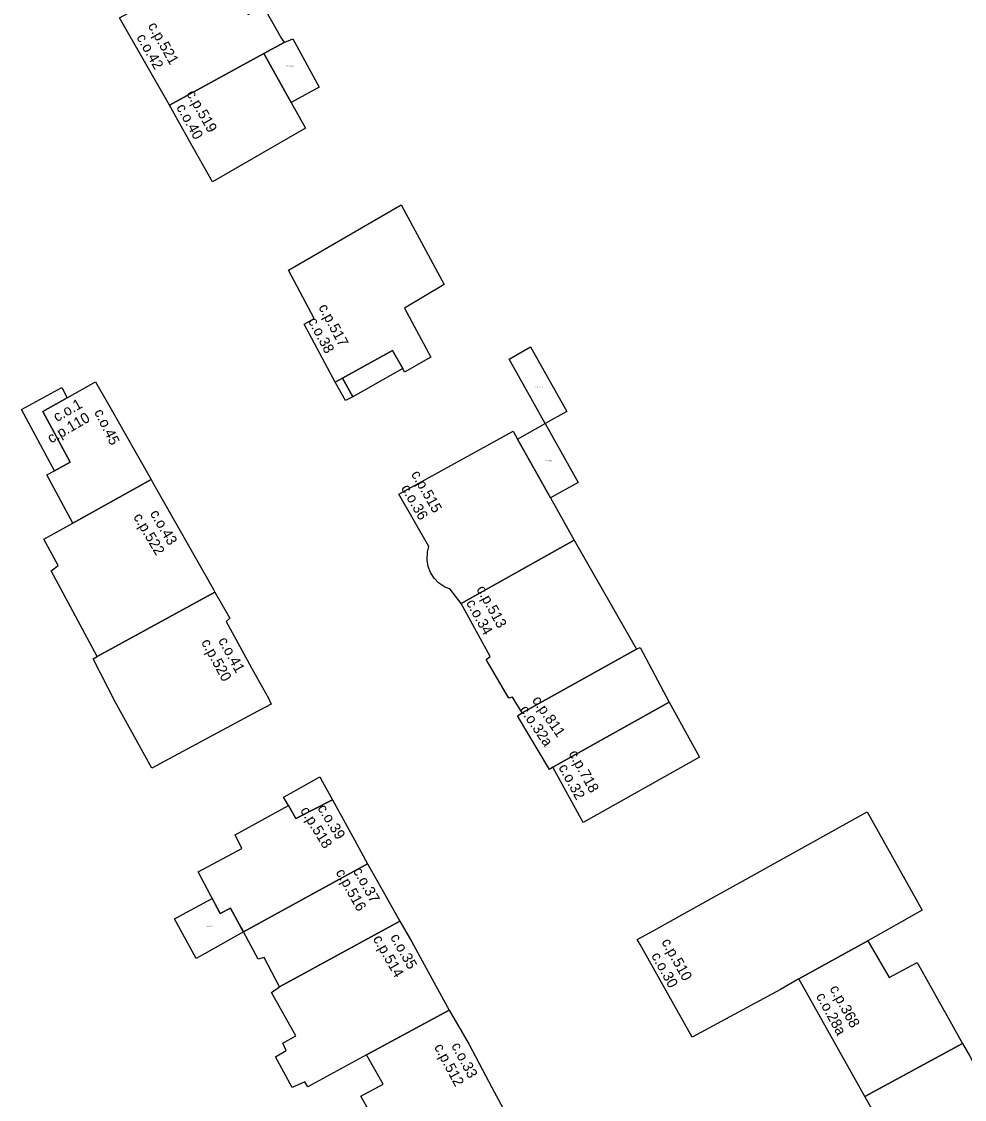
# Model space of a CAD drawing. Extents: x -600391 to -599491, y -1160176 to -1159402.
# Drawn here: x -600329.1 to -600239.1, y -1159820.9 to -1159718.1 of the extents above; entities that cross this region are included whole.
import ezdxf

# ---------------------------------------------------------------- set-up
doc = ezdxf.new("R2010")
doc.units = 0
for name, color, linetype in [('Level 10', 7, 'Continuous'), ('Level 12', 7, 'Continuous'), ('Level 25', 7, 'Continuous'), ('Level 61', 7, 'Continuous'), ('Level 62', 7, 'Continuous')]:
    doc.layers.add(name, color=color, linetype=linetype)

msp = doc.modelspace()

# ---------------------------------------------------------------- linework, layer by layer
at = {"layer": 'Level 61'}
for points in [[(-600306.02, -1159716.62), (-600304.28, -1159719.7)], [(-600314.98, -1159726.08), (-600319.73, -1159717.73)], [(-600304.28, -1159719.7), (-600304.03, -1159720.11)], [(-600304.03, -1159720.11), (-600303.21, -1159719.76)], [(-600303.21, -1159719.76), (-600300.69, -1159724.35)], [(-600304.03, -1159720.11), (-600305.98, -1159721.16)], [(-600305.98, -1159721.16), (-600304.03, -1159720.11)], [(-600305.98, -1159721.16), (-600314.98, -1159726.08)], [(-600314.98, -1159726.08), (-600305.98, -1159721.16)], [(-600305.98, -1159721.16), (-600303.36, -1159725.82)], [(-600303.36, -1159725.82), (-600305.98, -1159721.16)], [(-600300.69, -1159724.35), (-600303.36, -1159725.82)], [(-600313.98, -1159727.86), (-600314.98, -1159726.08)], [(-600303.36, -1159725.82), (-600301.99, -1159728.26)], [(-600313.82, -1159728.13), (-600313.98, -1159727.86)], [(-600313.29, -1159729.08), (-600313.82, -1159728.13)], [(-600313.05, -1159729.5), (-600313.29, -1159729.08)], [(-600301.99, -1159728.26), (-600310.86, -1159733.39)], [(-600310.86, -1159733.39), (-600313.05, -1159729.5)], [(-600303.61, -1159741.8), (-600292.85, -1159735.57)], [(-600292.85, -1159735.57), (-600288.77, -1159743.19)], [(-600301.17, -1159746.41), (-600303.61, -1159741.8)], [(-600288.77, -1159743.19), (-600292.56, -1159745.42)], [(-600292.56, -1159745.42), (-600290.03, -1159750.12)], [(-600302.11, -1159746.96), (-600301.17, -1159746.41)], [(-600299.17, -1159752.49), (-600302.11, -1159746.96)], [(-600298.45, -1159752.1), (-600293.69, -1159749.47)], [(-600293.69, -1159749.47), (-600298.45, -1159752.1)], [(-600293.69, -1159749.47), (-600292.72, -1159751.2)], [(-600292.72, -1159751.2), (-600293.69, -1159749.47)], [(-600282.56, -1159750.28), (-600280.51, -1159749.13)], [(-600280.51, -1159749.13), (-600277.07, -1159755.29)], [(-600290.03, -1159750.12), (-600292.55, -1159751.52)], [(-600279.11, -1159756.44), (-600282.56, -1159750.28)], [(-600292.72, -1159751.2), (-600297.48, -1159753.88)], [(-600292.55, -1159751.52), (-600292.72, -1159751.2)], [(-600324.72, -1159753.97), (-600322.02, -1159752.45)], [(-600322.02, -1159752.45), (-600320.4, -1159755.29)], [(-600298.45, -1159752.1), (-600299.17, -1159752.49)], [(-600299.17, -1159752.49), (-600298.45, -1159752.1)], [(-600298.16, -1159754.23), (-600299.17, -1159752.49)], [(-600297.48, -1159753.88), (-600298.45, -1159752.1)], [(-600298.45, -1159752.1), (-600297.48, -1159753.88)], [(-600329.08, -1159755.1), (-600325.25, -1159753)], [(-600325.25, -1159753), (-600324.72, -1159753.97)], [(-600297.48, -1159753.88), (-600298.16, -1159754.23)], [(-600327.04, -1159755.27), (-600324.72, -1159753.97)], [(-600324.72, -1159753.97), (-600327.04, -1159755.27)], [(-600325.94, -1159760.93), (-600329.08, -1159755.1)], [(-600324.43, -1159760.13), (-600327.04, -1159755.27)], [(-600327.04, -1159755.27), (-600324.43, -1159760.13)], [(-600320.4, -1159755.29), (-600319.32, -1159757.19)], [(-600277.07, -1159755.29), (-600279.11, -1159756.44)], [(-600281.75, -1159757.92), (-600279.11, -1159756.44)], [(-600279.11, -1159756.44), (-600275.97, -1159762.05)], [(-600319.32, -1159757.19), (-600316.72, -1159761.77)], [(-600293.08, -1159763.17), (-600282.17, -1159757.17)], [(-600282.17, -1159757.17), (-600281.75, -1159757.92)], [(-600281.75, -1159757.92), (-600278.62, -1159763.52)], [(-600278.62, -1159763.52), (-600281.75, -1159757.92)], [(-600326.67, -1159761.32), (-600325.94, -1159760.93)], [(-600325.94, -1159760.93), (-600324.43, -1159760.13)], [(-600324.43, -1159760.13), (-600325.94, -1159760.93)], [(-600324.18, -1159765.92), (-600326.67, -1159761.32)], [(-600324.18, -1159765.92), (-600316.72, -1159761.77)], [(-600316.72, -1159761.77), (-600324.18, -1159765.92)], [(-600316.72, -1159761.77), (-600316.58, -1159762.02)], [(-600316.58, -1159762.02), (-600316.45, -1159762.26)], [(-600275.97, -1159762.05), (-600278.62, -1159763.52)], [(-600316.45, -1159762.26), (-600312.78, -1159768.72)], [(-600290.22, -1159768.16), (-600293.08, -1159763.17)], [(-600278.62, -1159763.52), (-600276.37, -1159767.54)], [(-600326.96, -1159767.46), (-600324.18, -1159765.92)], [(-600325.6, -1159769.96), (-600326.96, -1159767.46)], [(-600290.35, -1159768.68), (-600290.22, -1159768.16)], [(-600287.15, -1159773.61), (-600276.37, -1159767.54)], [(-600276.37, -1159767.54), (-600287.15, -1159773.61)], [(-600276.37, -1159767.54), (-600270.4, -1159777.96)], [(-600312.78, -1159768.72), (-600310.81, -1159772.2)], [(-600290.39, -1159769.43), (-600290.35, -1159768.68)], [(-600326.26, -1159770.49), (-600325.6, -1159769.96)], [(-600290.3, -1159770.07), (-600290.39, -1159769.43)], [(-600290.07, -1159770.63), (-600290.3, -1159770.07)], [(-600321.85, -1159778.65), (-600326.26, -1159770.49)], [(-600289.72, -1159771.17), (-600290.07, -1159770.63)], [(-600289.31, -1159771.61), (-600289.72, -1159771.17)], [(-600310.81, -1159772.2), (-600310.64, -1159772.5)], [(-600288.73, -1159772), (-600289.31, -1159771.61)], [(-600288.19, -1159772.24), (-600288.73, -1159772)], [(-600287.15, -1159773.61), (-600288.19, -1159772.24)], [(-600310.64, -1159772.5), (-600321.85, -1159778.65)], [(-600321.85, -1159778.65), (-600310.64, -1159772.5)], [(-600310.64, -1159772.5), (-600309.2, -1159775)], [(-600284.37, -1159778.66), (-600287.15, -1159773.61)], [(-600309.2, -1159775), (-600309.56, -1159775.31)], [(-600309.56, -1159775.31), (-600306.96, -1159780.08)], [(-600270.4, -1159777.96), (-600281.32, -1159784.02)], [(-600281.32, -1159784.02), (-600270.4, -1159777.96)], [(-600270.4, -1159777.96), (-600270.06, -1159777.8)], [(-600270.06, -1159777.8), (-600267.31, -1159783.02)], [(-600322.24, -1159778.87), (-600321.85, -1159778.65)], [(-600320.14, -1159782.97), (-600322.24, -1159778.87)], [(-600284.75, -1159778.94), (-600284.37, -1159778.66)], [(-600282.59, -1159782.61), (-600284.75, -1159778.94)], [(-600306.96, -1159780.08), (-600305.51, -1159782.63)], [(-600305.51, -1159782.63), (-600305.27, -1159783.18)], [(-600282.23, -1159782.53), (-600282.59, -1159782.61)], [(-600281.32, -1159784.02), (-600282.23, -1159782.53)], [(-600316.64, -1159789.29), (-600320.14, -1159782.97)], [(-600305.27, -1159783.18), (-600307.03, -1159784.13)], [(-600267.31, -1159783.02), (-600278.4, -1159789.21)], [(-600278.4, -1159789.21), (-600267.31, -1159783.02)], [(-600267.31, -1159783.02), (-600264.4, -1159788.24)], [(-600307.03, -1159784.13), (-600316.64, -1159789.29)], [(-600281.75, -1159784.3), (-600281.32, -1159784.02)], [(-600278.72, -1159789.43), (-600281.75, -1159784.3)], [(-600264.4, -1159788.24), (-600275.51, -1159794.48)], [(-600278.4, -1159789.21), (-600278.72, -1159789.43)], [(-600275.51, -1159794.48), (-600278.4, -1159789.21)], [(-600303.38, -1159791.67), (-600300.61, -1159790.14)], [(-600300.61, -1159790.14), (-600300.37, -1159790.6)], [(-600300.37, -1159790.6), (-600299.43, -1159792.33)], [(-600304.08, -1159792.05), (-600303.38, -1159791.67)], [(-600308.7, -1159795.67), (-600303.62, -1159792.85)], [(-600303.62, -1159792.85), (-600304.08, -1159792.05)], [(-600303.62, -1159792.85), (-600302.91, -1159794.1)], [(-600302.91, -1159794.1), (-600303.62, -1159792.85)], [(-600302.91, -1159794.1), (-600299.43, -1159792.33)], [(-600299.43, -1159792.33), (-600302.91, -1159794.1)], [(-600299.43, -1159792.33), (-600297.51, -1159795.78)], [(-600261.16, -1159800.55), (-600248.4, -1159793.47)], [(-600248.4, -1159793.47), (-600243.17, -1159802.85)], [(-600308.05, -1159796.95), (-600308.7, -1159795.67)], [(-600297.51, -1159795.78), (-600296.06, -1159798.41)], [(-600312.23, -1159799.2), (-600308.05, -1159796.95)], [(-600296.06, -1159798.41), (-600307.89, -1159804.92)], [(-600307.89, -1159804.92), (-600296.06, -1159798.41)], [(-600296.06, -1159798.41), (-600295.02, -1159800.28)], [(-600310.12, -1159803.15), (-600312.23, -1159799.2)], [(-600295.02, -1159800.28), (-600293, -1159803.9)], [(-600262.73, -1159801.42), (-600261.16, -1159800.55)], [(-600314.5, -1159803.67), (-600310.88, -1159801.73)], [(-600310.88, -1159801.73), (-600310.12, -1159803.15)], [(-600267.45, -1159804.04), (-600262.73, -1159801.42)], [(-600310.12, -1159803.15), (-600309.13, -1159802.66)], [(-600309.13, -1159802.66), (-600310.12, -1159803.15)], [(-600309.13, -1159802.66), (-600308.13, -1159804.51)], [(-600308.13, -1159804.51), (-600309.13, -1159802.66)], [(-600243.17, -1159802.85), (-600248.34, -1159805.75)], [(-600312.41, -1159807.44), (-600314.5, -1159803.67)], [(-600293, -1159803.9), (-600304.47, -1159810.14)], [(-600304.47, -1159810.14), (-600293, -1159803.9)], [(-600293, -1159803.9), (-600291.85, -1159805.87)], [(-600268.77, -1159804.77), (-600267.45, -1159804.04)], [(-600307.89, -1159804.92), (-600310.83, -1159806.56)], [(-600308.13, -1159804.51), (-600307.89, -1159804.92)], [(-600307.89, -1159804.92), (-600308.13, -1159804.51)], [(-600306.5, -1159807.52), (-600307.89, -1159804.92)], [(-600270.34, -1159805.64), (-600268.77, -1159804.77)], [(-600291.85, -1159805.87), (-600290.66, -1159808.02)], [(-600270.06, -1159806.13), (-600270.34, -1159805.64)], [(-600265.1, -1159814.95), (-600270.06, -1159806.13)], [(-600248.34, -1159805.75), (-600254.91, -1159809.39)], [(-600254.91, -1159809.39), (-600248.34, -1159805.75)], [(-600248.34, -1159805.75), (-600246.3, -1159809.26)], [(-600310.83, -1159806.56), (-600312.41, -1159807.44)], [(-600305.93, -1159807.36), (-600306.5, -1159807.52)], [(-600304.47, -1159810.14), (-600305.93, -1159807.36)], [(-600290.66, -1159808.02), (-600288.29, -1159812.37)], [(-600246.3, -1159809.26), (-600243.65, -1159807.83)], [(-600243.65, -1159807.83), (-600239.3, -1159815.54)], [(-600254.91, -1159809.39), (-600256.68, -1159810.41)], [(-600248.62, -1159820.62), (-600254.91, -1159809.39)], [(-600305.23, -1159810.68), (-600304.47, -1159810.14)], [(-600256.68, -1159810.41), (-600265.1, -1159814.95)], [(-600302.92, -1159814.82), (-600305.23, -1159810.68)], [(-600296.16, -1159816.64), (-600288.29, -1159812.37)], [(-600288.29, -1159812.37), (-600296.16, -1159816.64)], [(-600288.29, -1159812.37), (-600286.39, -1159815.66)], [(-600304.16, -1159815.51), (-600302.92, -1159814.82)], [(-600303.84, -1159816.23), (-600304.16, -1159815.51)], [(-600239.3, -1159815.54), (-600248.62, -1159820.62)], [(-600248.62, -1159820.62), (-600239.3, -1159815.54)], [(-600239.3, -1159815.54), (-600238.62, -1159816.77)], [(-600304.86, -1159816.84), (-600303.84, -1159816.23)], [(-600286.39, -1159815.66), (-600284.2, -1159819.76)], [(-600303.27, -1159819.76), (-600304.86, -1159816.84)], [(-600296.16, -1159816.64), (-600301.78, -1159819.69)], [(-600294.57, -1159819.44), (-600296.16, -1159816.64)], [(-600302.05, -1159819.2), (-600303.27, -1159819.76)], [(-600301.78, -1159819.69), (-600302.05, -1159819.2)], [(-600296.72, -1159820.57), (-600294.57, -1159819.44)], [(-600290.35, -1159831.88), (-600296.72, -1159820.57)], [(-600284.2, -1159819.76), (-600280.6, -1159826.47)], [(-600240.34, -1159835.38), (-600248.62, -1159820.62)]]:
    msp.add_lwpolyline(points, dxfattribs=at)
at = {"layer": 'Level 62'}
for points in [[(-600305.98, -1159721.16), (-600314.98, -1159726.08), (-600319.73, -1159717.73), (-600316.55, -1159716), (-600312.59, -1159713.84), (-600310.26, -1159712.57), (-600307.47, -1159717.43), (-600306.02, -1159716.62), (-600304.28, -1159719.7), (-600304.03, -1159720.11), (-600305.98, -1159721.16)], [(-600300.69, -1159724.35), (-600303.36, -1159725.82), (-600305.98, -1159721.16), (-600304.03, -1159720.11), (-600303.21, -1159719.76), (-600300.69, -1159724.35)], [(-600314.98, -1159726.08), (-600305.98, -1159721.16), (-600303.36, -1159725.82), (-600301.99, -1159728.26), (-600310.86, -1159733.39), (-600313.05, -1159729.5), (-600313.29, -1159729.08), (-600313.82, -1159728.13), (-600313.98, -1159727.86), (-600314.98, -1159726.08)], [(-600299.17, -1159752.49), (-600302.11, -1159746.96), (-600301.17, -1159746.41), (-600303.61, -1159741.8), (-600292.85, -1159735.57), (-600288.77, -1159743.19), (-600292.56, -1159745.42), (-600290.03, -1159750.12), (-600292.55, -1159751.52), (-600292.72, -1159751.2), (-600293.69, -1159749.47), (-600298.45, -1159752.1), (-600299.17, -1159752.49)], [(-600297.48, -1159753.88), (-600298.45, -1159752.1), (-600293.69, -1159749.47), (-600292.72, -1159751.2), (-600297.48, -1159753.88)], [(-600280.51, -1159749.13), (-600277.07, -1159755.29), (-600279.11, -1159756.44), (-600282.56, -1159750.28), (-600280.51, -1159749.13)], [(-600319.32, -1159757.19), (-600316.72, -1159761.77), (-600324.18, -1159765.92), (-600326.67, -1159761.32), (-600325.94, -1159760.93), (-600324.43, -1159760.13), (-600327.04, -1159755.27), (-600324.72, -1159753.97), (-600322.02, -1159752.45), (-600320.4, -1159755.29), (-600319.32, -1159757.19)], [(-600299.17, -1159752.49), (-600298.45, -1159752.1), (-600297.48, -1159753.88), (-600298.16, -1159754.23), (-600299.17, -1159752.49)], [(-600325.25, -1159753), (-600324.72, -1159753.97), (-600327.04, -1159755.27), (-600324.43, -1159760.13), (-600325.94, -1159760.93), (-600329.08, -1159755.1), (-600325.25, -1159753)], [(-600281.75, -1159757.92), (-600279.11, -1159756.44), (-600275.97, -1159762.05), (-600278.62, -1159763.52), (-600281.75, -1159757.92)], [(-600281.75, -1159757.92), (-600278.62, -1159763.52), (-600276.37, -1159767.54), (-600287.15, -1159773.61), (-600288.19, -1159772.24), (-600288.73, -1159772), (-600289.31, -1159771.61), (-600289.72, -1159771.17), (-600290.07, -1159770.63), (-600290.3, -1159770.07), (-600290.39, -1159769.43), (-600290.35, -1159768.68), (-600290.22, -1159768.16), (-600293.08, -1159763.17), (-600282.17, -1159757.17), (-600281.75, -1159757.92)], [(-600310.81, -1159772.2), (-600310.64, -1159772.5), (-600321.85, -1159778.65), (-600326.26, -1159770.49), (-600325.6, -1159769.96), (-600326.96, -1159767.46), (-600324.18, -1159765.92), (-600316.72, -1159761.77), (-600316.58, -1159762.02), (-600316.45, -1159762.26), (-600312.78, -1159768.72), (-600310.81, -1159772.2)], [(-600270.4, -1159777.96), (-600281.32, -1159784.02), (-600282.23, -1159782.53), (-600282.59, -1159782.61), (-600284.75, -1159778.94), (-600284.37, -1159778.66), (-600287.15, -1159773.61), (-600276.37, -1159767.54), (-600270.4, -1159777.96)], [(-600305.51, -1159782.63), (-600305.27, -1159783.18), (-600307.03, -1159784.13), (-600316.64, -1159789.29), (-600320.14, -1159782.97), (-600322.24, -1159778.87), (-600321.85, -1159778.65), (-600310.64, -1159772.5), (-600309.2, -1159775), (-600309.56, -1159775.31), (-600306.96, -1159780.08), (-600305.51, -1159782.63)], [(-600278.72, -1159789.43), (-600281.75, -1159784.3), (-600281.32, -1159784.02), (-600270.4, -1159777.96), (-600270.06, -1159777.8), (-600267.31, -1159783.02), (-600278.4, -1159789.21), (-600278.72, -1159789.43)], [(-600278.4, -1159789.21), (-600267.31, -1159783.02), (-600264.4, -1159788.24), (-600275.51, -1159794.48), (-600278.4, -1159789.21)], [(-600303.38, -1159791.67), (-600300.61, -1159790.14), (-600300.37, -1159790.6), (-600299.43, -1159792.33), (-600302.91, -1159794.1), (-600303.62, -1159792.85), (-600304.08, -1159792.05), (-600303.38, -1159791.67)], [(-600303.62, -1159792.85), (-600302.91, -1159794.1), (-600299.43, -1159792.33), (-600297.51, -1159795.78), (-600296.06, -1159798.41), (-600307.89, -1159804.92), (-600308.13, -1159804.51), (-600309.13, -1159802.66), (-600310.12, -1159803.15), (-600312.23, -1159799.2), (-600308.05, -1159796.95), (-600308.7, -1159795.67), (-600303.62, -1159792.85)], [(-600267.45, -1159804.04), (-600262.73, -1159801.42), (-600261.16, -1159800.55), (-600248.4, -1159793.47), (-600243.17, -1159802.85), (-600248.34, -1159805.75), (-600254.91, -1159809.39), (-600256.68, -1159810.41), (-600265.1, -1159814.95), (-600270.06, -1159806.13), (-600270.34, -1159805.64), (-600268.77, -1159804.77), (-600267.45, -1159804.04)], [(-600296.06, -1159798.41), (-600295.02, -1159800.28), (-600293, -1159803.9), (-600304.47, -1159810.14), (-600305.93, -1159807.36), (-600306.5, -1159807.52), (-600307.89, -1159804.92), (-600296.06, -1159798.41)], [(-600312.41, -1159807.44), (-600314.5, -1159803.67), (-600310.88, -1159801.73), (-600310.12, -1159803.15), (-600309.13, -1159802.66), (-600308.13, -1159804.51), (-600307.89, -1159804.92), (-600310.83, -1159806.56), (-600312.41, -1159807.44)], [(-600305.23, -1159810.68), (-600304.47, -1159810.14), (-600293, -1159803.9), (-600291.85, -1159805.87), (-600290.66, -1159808.02), (-600288.29, -1159812.37), (-600296.16, -1159816.64), (-600301.78, -1159819.69), (-600302.05, -1159819.2), (-600303.27, -1159819.76), (-600304.86, -1159816.84), (-600303.84, -1159816.23), (-600304.16, -1159815.51), (-600302.92, -1159814.82), (-600305.23, -1159810.68)], [(-600254.91, -1159809.39), (-600248.34, -1159805.75), (-600246.3, -1159809.26), (-600243.65, -1159807.83), (-600239.3, -1159815.54), (-600248.62, -1159820.62), (-600254.91, -1159809.39)], [(-600288.29, -1159812.37), (-600286.39, -1159815.66), (-600284.2, -1159819.76), (-600280.6, -1159826.47), (-600290.35, -1159831.88), (-600296.72, -1159820.57), (-600294.57, -1159819.44), (-600296.16, -1159816.64), (-600288.29, -1159812.37)], [(-600231.22, -1159830.2), (-600240.34, -1159835.38), (-600248.62, -1159820.62), (-600239.3, -1159815.54), (-600238.62, -1159816.77), (-600237.94, -1159818), (-600232.57, -1159827.75), (-600231.9, -1159828.97), (-600231.22, -1159830.2)]]:
    msp.add_lwpolyline(points, dxfattribs=at)

# ---------------------------------------------------------------- texts
at = {"layer": 'Level 10'}
for s, rotation, p in [('c.o.42', 299.6362, (-600318.15, -1159719.6)), ('c.o.40', 299.4052, (-600314.35, -1159726.28)), ('c.o.38', 297.995, (-600301.78, -1159746.64)), ('c.o.1', 29.9929, (-600325.7, -1159756.31)), ('c.o.45', 296.3344, (-600322.18, -1159755.33)), ('c.o.36', 299.8209, (-600292.91, -1159762.58)), ('c.o.43', 300.6247, (-600316.87, -1159765.01)), ('c.o.34', 298.8359, (-600286.7, -1159773.52)), ('c.o.41', 298.7385, (-600310.35, -1159777.12)), ('c.o.32a', 304.3067, (-600281.61, -1159783.72)), ('c.o.32', 298.7385, (-600277.89, -1159789.22)), ('c.o.39', 301.7606, (-600300.89, -1159793.11)), ('c.o.37', 299.2282, (-600297.49, -1159799.08)), ('c.o.35', 299.5978, (-600293.94, -1159805.41)), ('c.o.30', 299.1976, (-600269.04, -1159807.18)), ('c.o.28a', 298.5487, (-600253.32, -1159811.03)), ('c.o.33', 298.1052, (-600288.11, -1159815.76))]:
    msp.add_text(s, height=1, rotation=rotation, dxfattribs=at).set_placement(p)
at = {"layer": 'Level 12'}
for s, rotation, p in [('c.p.521', 299.6362, (-600317.06, -1159718.5)), ('c.p.519', 299.4052, (-600313.38, -1159724.97)), ('c.p.517', 297.995, (-600300.78, -1159745.34)), ('c.p.110', 29.9929, (-600326.26, -1159758.36)), ('c.p.515', 299.8209, (-600291.95, -1159761.25)), ('c.p.522', 300.6247, (-600318.45, -1159765.33)), ('c.p.513', 298.8359, (-600285.72, -1159772.21)), ('c.p.520', 298.7385, (-600311.97, -1159777.29)), ('c.p.811', 304.3067, (-600280.42, -1159782.82)), ('c.p.718', 298.7385, (-600276.92, -1159787.9)), ('c.p.518', 301.7606, (-600302.53, -1159793.33)), ('c.p.516', 299.2282, (-600299.14, -1159799.22)), ('c.p.514', 299.5978, (-600295.59, -1159805.56)), ('c.p.510', 299.1976, (-600268.06, -1159805.86)), ('c.p.368', 298.5487, (-600252.02, -1159810.31)), ('c.p.512', 298.1052, (-600289.75, -1159815.88))]:
    msp.add_text(s, height=1, rotation=rotation, dxfattribs=at).set_placement(p)
at = {"layer": 'Level 25'}
for s, p in [('c.pp.519_A', (-600303.85, -1159722.36)), ('c.pp.515_A', (-600280.03, -1159752.99)), ('c.pp.515_B', (-600279.16, -1159760)), ('c.pp.518_A', (-600311.49, -1159804.42))]:
    msp.add_text(s, height=0.1, dxfattribs=at).set_placement(p)

doc.saveas('drawing.dxf')
